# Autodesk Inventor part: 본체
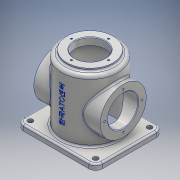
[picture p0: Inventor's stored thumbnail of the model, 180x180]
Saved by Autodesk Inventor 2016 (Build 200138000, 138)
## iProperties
Created: 2021-02
Part Number: 본체
Material: 알루미늄 6061
Document SubType Name: Modeling
Designer: user
Density: 2.7 g/cm^3
Appearance: 알루미늄 - 평지
Mass: 1186.99 g
Surface Area: 1041.94 cm^2
Volume: 439.628 cm^3
Author: user
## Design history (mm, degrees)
sketch "스케치12"
  geometry: L1 (70, -60)-(-70, -60); L2 (-70, -60)-(-70, 60); L3 (-70, 60)-(70, 60); L4 (70, 60)-(70, -60); L5 (70, -60)-(-70, 60); L6 (-70, -60)-(70, 60); 1 further point
  constraints: 12 end point, 2 midpoint, 2 parallel, 1 horizontal, 1 perpendicular
  dimensions: "d99" = 140 distance of L2.end L3.end; "d100" = 120 distance of L1.end L2.end
extrude "돌출5" new body sketch "스케치12" distance "d101" = 10; taper "d102" = 0 deg
fillet "모깎기5" dims "d103" = 12
hole "구멍7" diameter "d106" = 9; stored, may be unused: countersink angle "d110" = 90 deg, drill point angle "d112" = 118 deg; dims "d104" = 10, "d105" = 10, "d107" = 8, "d108" = 4, "d109" = 2, "d111" = 10
sketch "스케치13"
  geometry: C1 r 50 at (0, 0); 1 further point
  constraints: 1 centre point, 1 coincident
  dimensions: "d119" = 100 diameter of C1
extrude "돌출6" join sketch "스케치13" distance "d120" = 110; taper "d121" = 0 deg
sketch "스케치15"
  geometry: C1 r 42 at (0, 0); 1 further point
  constraints: 1 centre point, 1 coincident
  dimensions: "d122" = 84 diameter of C1
sketch "스케치16"
  geometry: C1 r 41 at (0, 0); 1 further point
  constraints: 1 centre point, 1 coincident
  dimensions: "d123" = 82 diameter of C1
extrude "돌출7" join sketch "스케치16" distance "d124" = 5; taper "d125" = 0 deg
hole "구멍8" sketch "스케치15" diameter "d126" = 54; stored, may be unused: countersink angle "d130" = 90 deg, drill point angle "d132" = 118 deg; dims "d127" = 8, "d128" = 84, "d129" = 112, "d131" = 10
fillet "모깎기6" dims "d133" = 3
fillet "모깎기7" dims "d134" = 3
node "작업 평면7"
sketch "스케치17"
  geometry: L1 (48, 0)-(-48, 0) reference; C1 r 41 at (0, 60); 2 further points
  constraints: 1 centre point, 1 midpoint, 1 vertical alignment
  dimensions: "d136" = 82 diameter of C1; "d137" = 60 distance from line of L1 C1.centre
extrude "돌출8" join sketch "스케치17" stored distance "d138" = 5; taper "d139" = 0 deg
hole "구멍9" diameter "d142" = 54; stored, may be unused: countersink angle "d146" = 90 deg, drill point angle "d148" = 118 deg; dims "d140" = 10, "d141" = 10, "d143" = 8, "d144" = 84, "d145" = 112, "d147" = 10
sketch "스케치18"
  geometry: L1 (0, 0)-(-33, 0); C1 r 27 at (0, 0) reference; 1 further point
  constraints: 2 end point, 1 coincident, 1 horizontal
  dimensions: "d149" = 33 distance of L1.start L1.end
hole "구멍10" sketch "스케치18" at (-33, 0) diameter "d150" = 3.242; stored, may be unused: countersink angle "d154" = 90 deg, drill point angle "d156" = 118 deg; dims "d151" = 8, "d152" = 84, "d153" = 112, "d155" = 10
sketch "스케치19"
  geometry: L1 (0, 0)-(-33, 0)
  constraints: 2 end point, 1 horizontal
  dimensions: "d160" = 33 distance of L1.start L1.end
hole "구멍11" sketch "스케치19" at (-33, 0) diameter "d161" = 3.242; stored, may be unused: countersink angle "d165" = 90 deg, drill point angle "d167" = 118 deg; dims "d162" = 8, "d163" = 84, "d164" = 112, "d166" = 10
chamfer "모따기2" distance "d171" = 1; stored, may be unused: second distance "d172" = 2, angle "d173" = 45 deg
fillet "모깎기8" dims "d174" = 6
fillet "모깎기9" dims "d175" = 3
node "작업 평면8"
sketch "스케치20"
  geometry: L1 (58, 0)-(-58, 0) reference; 3 further points
  constraints: 1 midpoint, 1 vertical alignment, 1 other
  dimensions: "d177" = 66 distance from line of L1 point (0, 66)
feature "엠보싱3" sketch "스케치20" dims "d99" = 140, "d100" = 120, "d118" = 116, "d178" = 0.5, "d179" = 0
node "솔리드2"
pattern_linear "직사각형 패턴2" dims "d115" = 96, "d118" = 116
mirror "대칭3"
pattern_circular "원형 패턴3" dims angle "d158" = 360 deg
mirror "대칭4"
pattern_circular "원형 패턴4" dims angle "d169" = 360 deg
other parameters: "d135" = 59, "d176" = -54.75
